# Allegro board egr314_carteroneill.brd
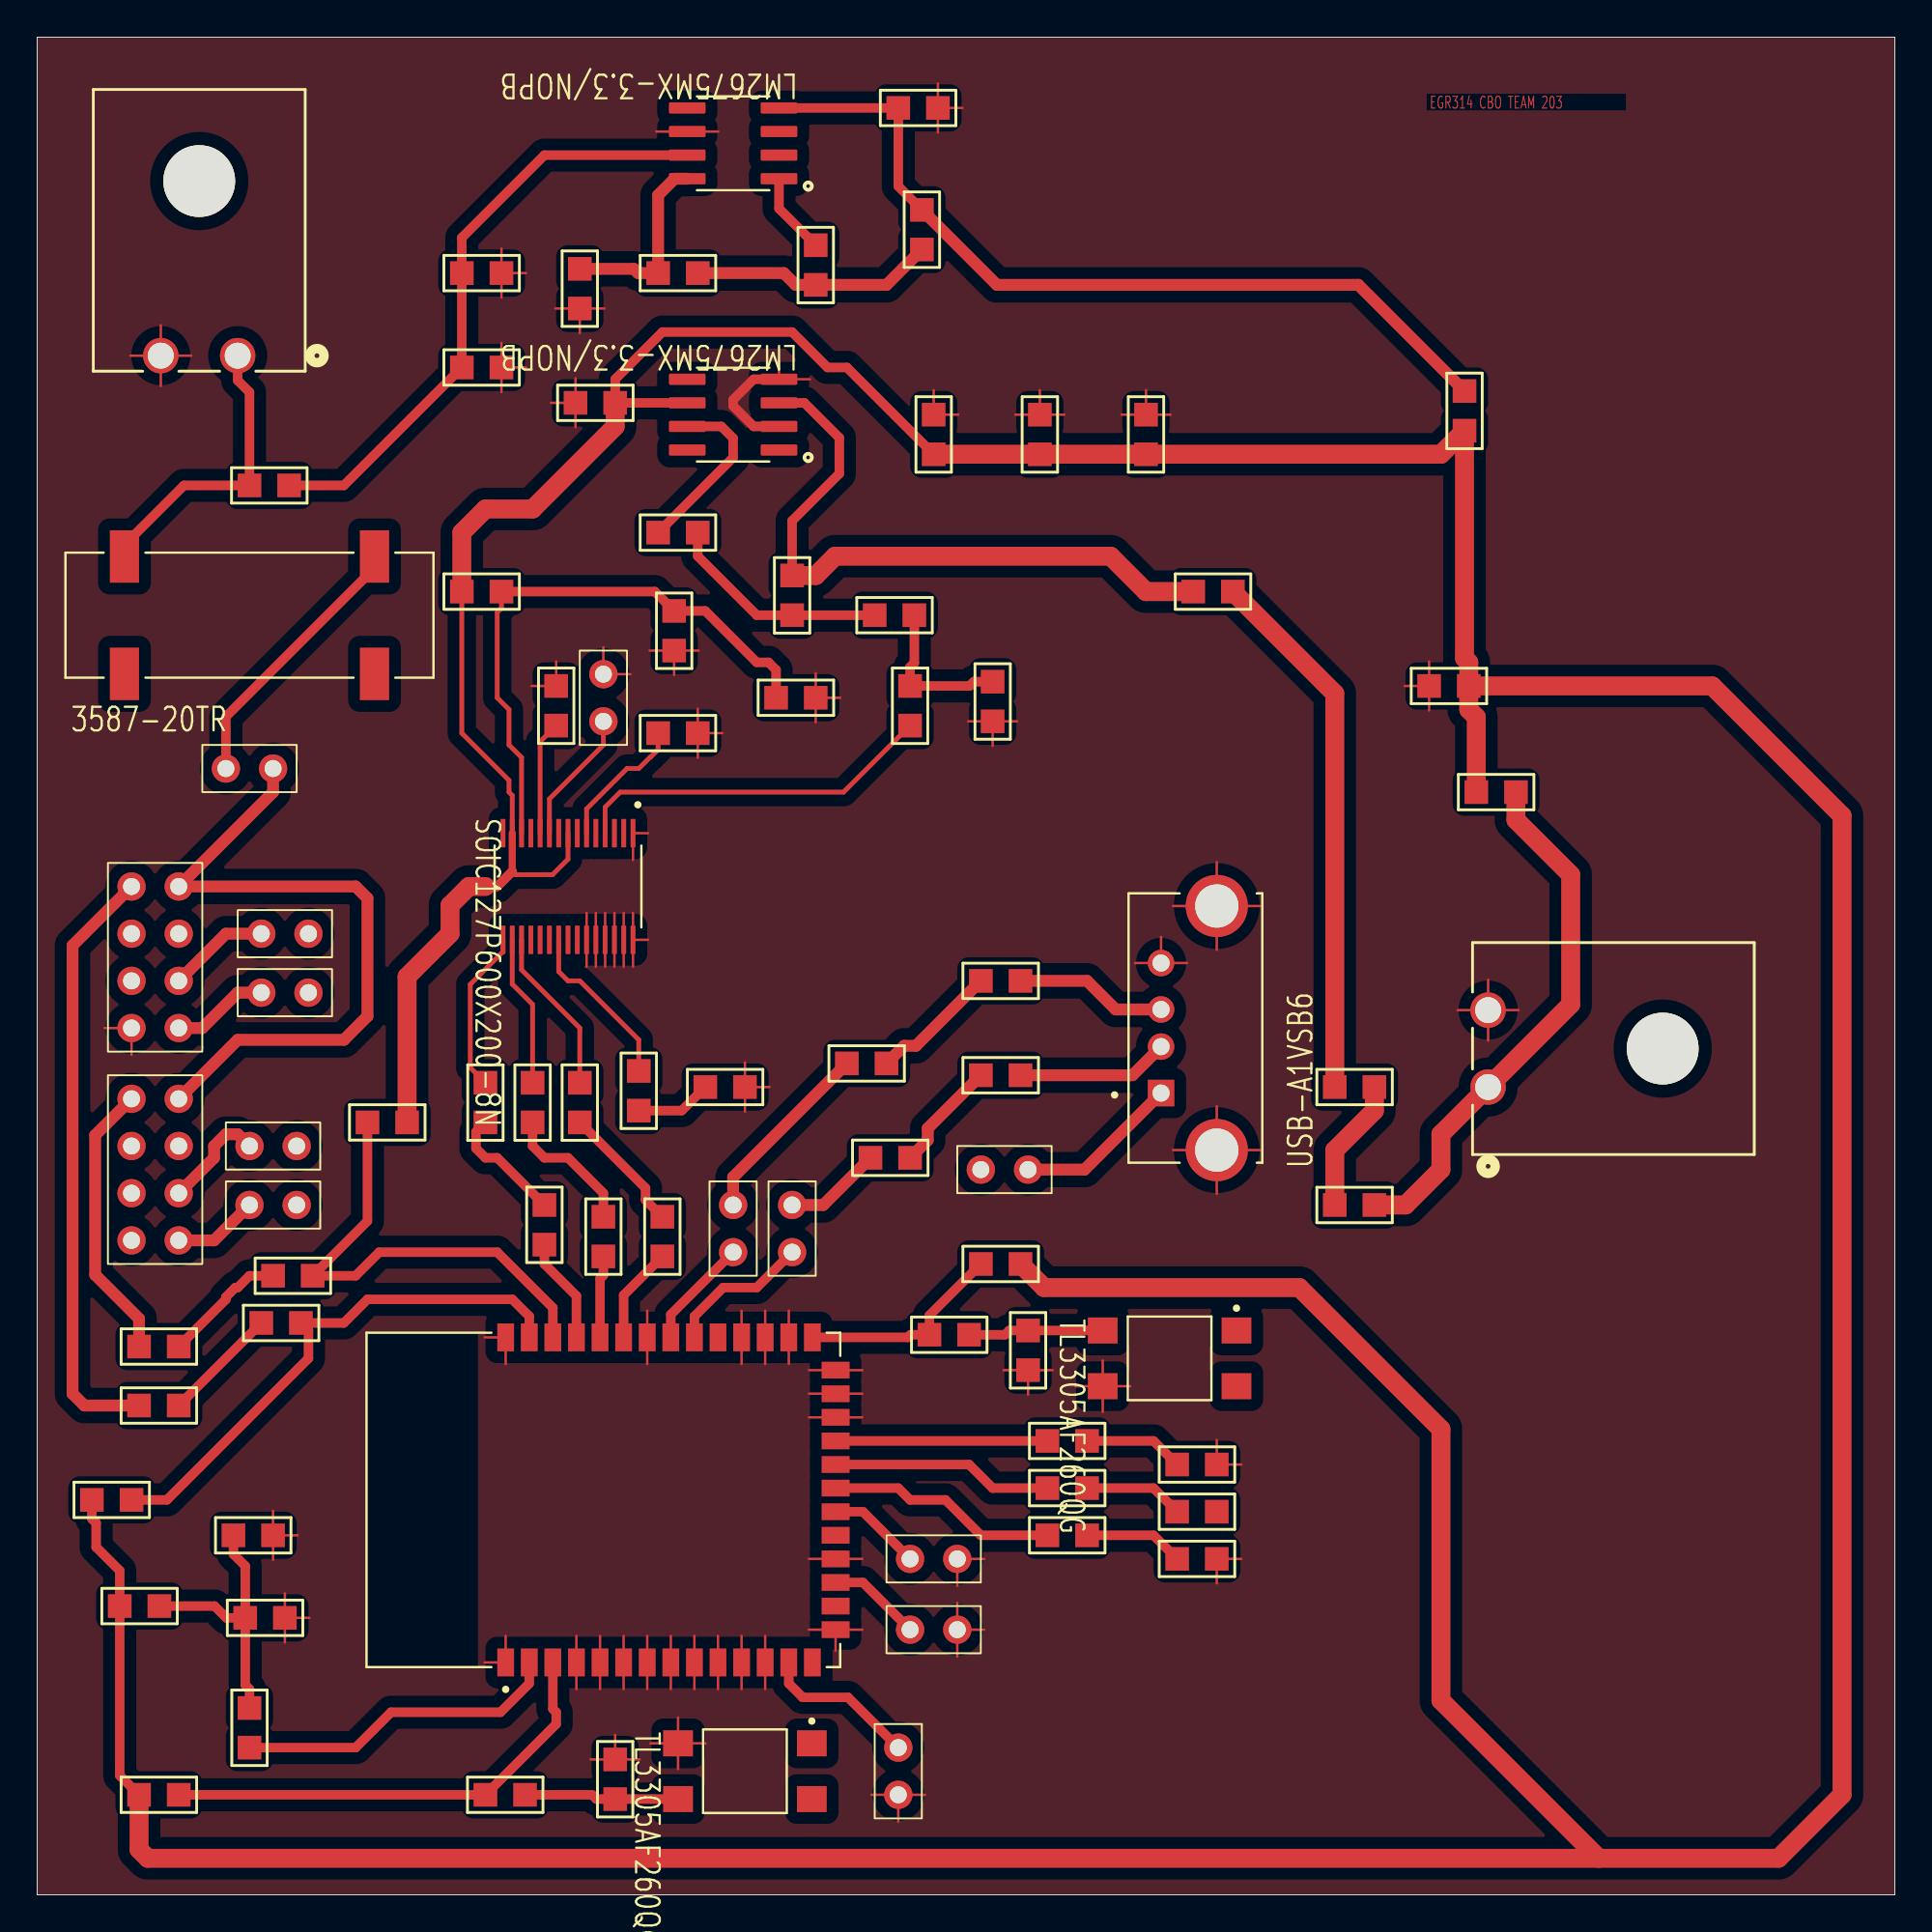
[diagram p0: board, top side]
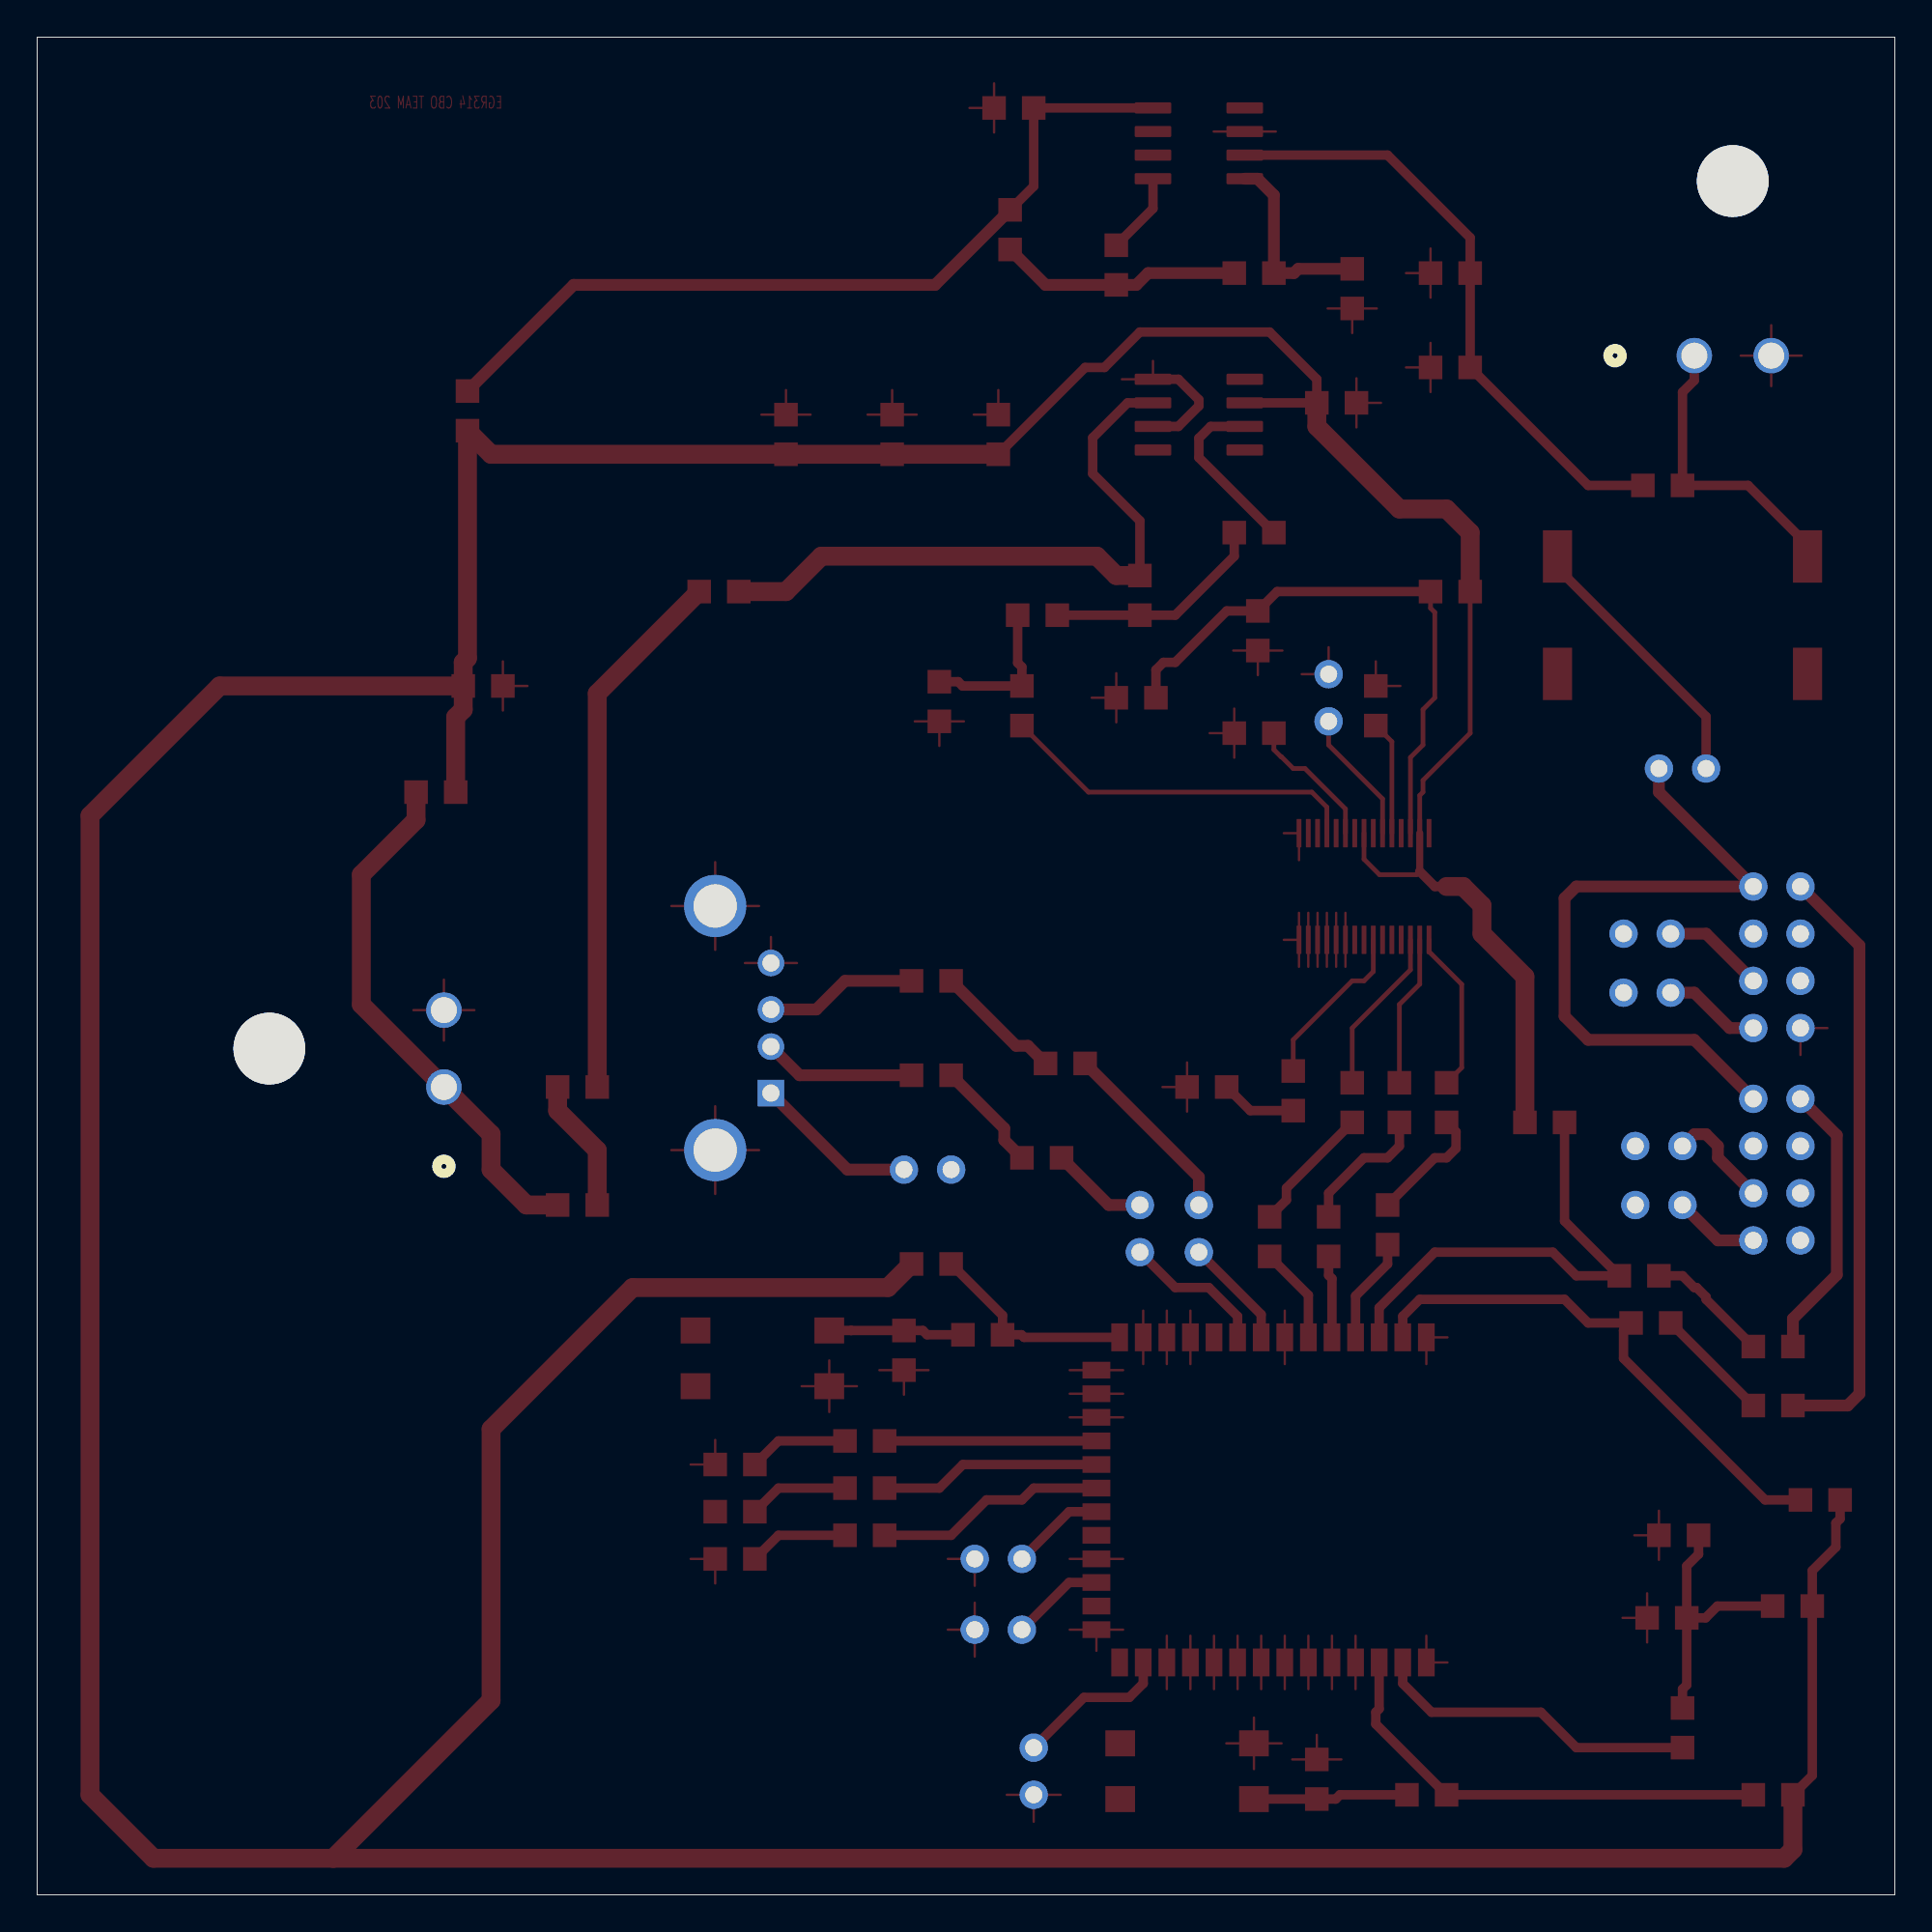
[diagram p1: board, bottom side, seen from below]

Outline 100 x 100 mm; copper layers: TOP, BOTTOM. Coordinates in mm from the lower left corner of the outline.
Outline path: 0,100 0,0 100,0 100,100 0,100

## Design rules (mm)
constraint set DEFAULT: min track width 0.127

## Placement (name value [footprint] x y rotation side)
C1  1uf  [SMC0805]  35.56 62.54 180 top
C2  10uf  [SMC0805]  53.98 79.68 270 top
C3  0.1uf  [SMC0805]  59.69 79.68 270 top
C4  10uf  [SMC0805]  41.91 64.44 180 top
C5  0.1uf  [SMC0805]  34.29 66.98 90 top
C6  10uf  [SMC0805]  48.26 79.68 270 top
C7  0.1uf  [SMC0805]  74.93 65.08 0 top
C8  1uf  [SMC0805]  27.94 65.08 270 top
C9  100uf/20V  [SMC0805]  22.86 87.3 0 top
C10  0.01uF  [SMC0805]  41.91 86.67 90 top
C11  594D 68uf/10V  [SMC0805]  46.35 96.19 0 top
C12  10uf/20V  [SMC0805]  22.86 82.22 0 top
C13  10uf  [SMC0805]  12.7 19.36 180 top
C14  0.1uf  [SMC0805]  13.34 14.91 180 top
C15  0.1uf  [SMC0805]  31.11 7.29 270 top
C16  0.5uF  [SMC0805]  51.44 63.17 90 top
C17  0.1uf  [SMC0805]  53.34 28.25 90 top
C18  1uf  [SMC0805]  69.85 37.14 0 top
C19  .1uf/20V  [SMC0805]  31.11 80.32 180 top
D1  LED  [SMR0805]  38.1 43.49 180 top
D2  SK12  [SMR0805]  29.21 85.4 90 top
D3  LED  [SMR0805]  63.5 18.09 180 top
D4  LED  [SMR0805]  63.5 20.63 180 top
D5  LED  [SMR0805]  63.5 23.17 180 top
F1  Fuse_CBO  [FUSE_3587-20TR]  11.43 68.89 0 top
F2  0.5A  [SMR0805]  4.45 15.55 0 top
J1  Input Header  [JUMPER8]  7.62 42.85 180 top
J2  JUMPER  [JUMPER2]  13.97 37.14 180 top
J3  JUMPER  [JUMPER2]  13.97 40.31 180 top
J4  JUMPER  [JUMPER2]  14.61 48.57 180 top
J5  JUMPER  [JUMPER2]  14.61 51.74 180 top
J6  Output Header  [JUMPER8]  7.62 54.28 180 top
J7  USB_Header_CBO  [ONSHORE_USB-A1VSB6]  63.5 46.66 90 top
J8  JUMPER  [JUMPER2]  10.16 60.63 0 top
J9  JUMPER  [JUMPER2]  50.8 39.04 0 top
J10  JUMPER  [JUMPER2]  30.48 63.17 90 top
J11  9V Barrel Jack  [CONN2_770966-2]  10.79 82.86 180 top
J12  JUMPER  [JUMPER2]  37.47 37.14 270 top
J13  JUMPER  [JUMPER2]  40.64 37.14 270 top
J14  JUMPER  [JUMPER2]  46.35 7.93 270 top
J15  JUMPER  [JUMPER2]  46.99 14.28 0 top
J16  JUMPER  [JUMPER2]  46.99 18.09 0 top
J17  Electret Microphone  [CONN2_770966-2]  78.11 43.49 90 top
L1  47uH  [SMR0805]  47.62 88.57 90 top
R1  0  [SMR0805]  7.62 29.52 180 top
R2  0  [SMR0805]  22.86 70.16 0 top
R3  400  [SMR0805]  32.38 42.22 90 top
R4  0  [SMR0805]  29.21 41.58 90 top
R5  0  [SMR0805]  50.8 49.2 0 top
R6  0  [SMR0805]  50.8 44.12 0 top
R7  0  [SMR0805]  26.67 41.58 90 top
R8  0  [SMR0805]  7.62 26.34 180 top
R9  0  [SMR0805]  24.13 41.58 90 top
R10  0  [SMR0805]  11.43 75.87 0 top
R11  0  [SMR0805]  76.83 80.95 270 top
R12  10K  [SMR0805]  7.62 5.39 180 top
R13  10K  [SMR0805]  50.8 33.96 0 top
R14  0  [SMR0805]  30.48 36.5 270 top
R15  10K  [SMR0805]  5.08 21.26 180 top
R16  0  [SMR0805]  35.56 87.3 180 top
R17  0  [SMR0805]  11.43 7.93 90 top
R18  10K  [SMR0805]  17.78 41.58 0 top
R19  0  [SMR0805]  27.3 37.14 270 top
R20  0  [SMR0805]  12.06 30.79 0 top
R21  0  [SMR0805]  24.13 5.39 0 top
R22  0  [SMR0805]  12.7 33.33 0 top
R23  0  [SMR0805]  33.66 36.5 270 top
R24  0  [SMR0805]  45.72 44.76 180 top
R25  0  [SMR0805]  46.99 39.68 180 top
R26  0  [SMR0805]  50.16 30.15 180 top
R27  RESISTOR TBD  [SMR0805]  40.64 68.89 90 top
R28  4K  [SMR0805]  45.09 68.89 0 top
R29  400  [SMR0805]  56.52 19.36 180 top
R30  400  [SMR0805]  56.52 21.9 180 top
R31  400  [SMR0805]  56.52 24.44 180 top
R32  0  [SMR0805]  35.56 73.33 180 top
R33  2.2k  [SMR0805]  77.47 59.36 0 top
R34  0  [SMR0805]  46.99 65.08 270 top
R35  0  [SMR0805]  69.85 43.49 0 top
R36  RESISTOR TBD  [SMR0805]  62.23 70.16 0 top
SW1  Pushbutton_CBO  [SW_TL3305AF260QG]  38.1 6.66 270 top
SW2  Pushbutton_CBO  [SW_TL3305AF260QG]  60.96 28.88 270 top
U1  PCM1861_CBO  [SOP50P640X120-30N]  28.57 54.28 270 top
U2  ESP32_WROOM_CBO  [XCVR_ESP32-S3-WROOM-1-N4]  30.48 21.26 90 top
U3  LM2675_CBO  [SOIC127P599X175-8N]  37.47 94.29 180 top
U4  TLV2371_CBO  [SOIC127P599X175-8N]  37.47 79.68 180 top

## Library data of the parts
C1-C8 C13-C18 = CAP NP
C9 C11 C12 C19 = CAP
C10 = CAPACITOR NON-POL
D1 D3-D5 = LED
D2 = DIODE SCHOTTKY
F1 = Fuse_CBO
F2 = FUSE
J1 J6 = CON8: User Part Number: ***
J2-J5 J8-J10 J12-J16 = JUMPER: User Part Number: ***
J7 = USB_Header_CBO
J11 J17 = CON2: User Part Number: PN; Tolerance: TOL
L1 = INDUCTOR
R1-R36 = RESISTOR
SW1 SW2 = Pushbutton_CBO
U1 = PCM1861_CBO
U2 = ESP32_WROOM_CBO
U3 = LM2675_CBO
U4 = TLV2371_CBO

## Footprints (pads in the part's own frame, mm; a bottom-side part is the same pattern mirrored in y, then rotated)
CONN2_770966-2
  round 3.861 hole 3.861 unplated: (2.07,-9.398)
  round 1.905 hole 1.397: 1(0,0) 2(4.14,0)
FUSE_3587-20TR
  rect 1.57x2.82 smd: 1_1(-6.73,3.16) 1_2(-6.73,-3.16) 2_1(6.73,3.16) 2_2(6.73,-3.16)
JUMPER2
  round 1.524 hole 0.914: 1(0,0) 2(2.54,0)
JUMPER8
  round 1.524 hole 0.914: 1(0,0) 2(2.54,0) 3(0,2.54) 4(2.54,2.54) 5(0,5.08) 6(2.54,5.08) 7(0,7.62) 8(2.54,7.62)
ONSHORE_USB-A1VSB6
  rect 1.428x1.428 hole 0.92: 1(-3.5,3)
  round 1.428 hole 0.92: 2(-1,3) 3(1,3) 4(3.5,3)
  round 3.346 hole 2.33: S1(-6.57,0) S2(6.57,0)
SMC0805
  rect 1.27x1.27 smd: 1(0,0) 2(2.134,0)
SMR0805
  rect 1.27x1.27 smd: 1(0,0) 2(2.134,0)
SOIC127P599X175-8N
  custom 0.15x0.15 smd: 1(-2.47,1.905) 2(-2.47,0.635) 3(-2.47,-0.635) 4(-2.47,-1.905) 5(2.47,-1.905) 6(2.47,-0.635) 7(2.47,0.635) 8(2.47,1.905)
SOP50P640X120-30N
  custom 0.065x0.065 smd: 1(-2.87,3.5) 2(-2.87,3) 3(-2.87,2.5) 4(-2.87,2) 5(-2.87,1.5) 6(-2.87,1) 7(-2.87,0.5) 8(-2.87,0) 9(-2.87,-0.5) 10(-2.87,-1) 11(-2.87,-1.5) 12(-2.87,-2) 13(-2.87,-2.5) 14(-2.87,-3) 15(-2.87,-3.5) 16(2.87,-3.5) 17(2.87,-3) 18(2.87,-2.5) 19(2.87,-2) 20(2.87,-1.5) 21(2.87,-1) 22(2.87,-0.5) 23(2.87,0) 24(2.87,0.5) 25(2.87,1) 26(2.87,1.5) 27(2.87,2) 28(2.87,2.5) 29(2.87,3) 30(2.87,3.5)
SW_TL3305AF260QG
  rect 1.4x1.6 smd: 1(-1.5,3.6) 2(-1.5,-3.6) 3(1.5,3.6) 4(1.5,-3.6)
XCVR_ESP32-S3-WROOM-1-N4
  rect 1.5x0.9 smd: 1(-8.75,5.26) 2(-8.75,3.99) 3(-8.75,2.72) 4(-8.75,1.45) 5(-8.75,0.18) 6(-8.75,-1.09) 7(-8.75,-2.36) 8(-8.75,-3.63) 9(-8.75,-4.9) 10(-8.75,-6.17) 11(-8.75,-7.44) 12(-8.75,-8.71) 13(-8.75,-9.98) 14(-8.75,-11.25) 27(8.75,-11.25) 28(8.75,-9.98) 29(8.75,-8.71) 30(8.75,-7.44) 31(8.75,-6.17) 32(8.75,-4.9) 33(8.75,-3.63) 34(8.75,-2.36) 35(8.75,-1.09) 36(8.75,0.18) 37(8.75,1.45) 38(8.75,2.72) 39(8.75,3.99) 40(8.75,5.26)
  rect 0.9x1.5 smd: 15(-6.985,-12.5) 16(-5.715,-12.5) 17(-4.445,-12.5) 18(-3.175,-12.5) 19(-1.905,-12.5) 20(-0.635,-12.5) 21(0.635,-12.5) 22(1.905,-12.5) 23(3.175,-12.5) 24(4.445,-12.5) 25(5.715,-12.5) 26(6.985,-12.5)

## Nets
3.3V POWER: C2.2 C3.2 C6.2 C7.2 C19.1 F2.1 R2.1 R11.2 R12.2 R13.2 R15.2 R18.2 R33.1 U1.8 U1.14 U4.6(VDD)
GND_POWER: C1.1 C2.1 C3.1 C4.1 C5.1 C6.1 C7.1 C8.1 C9.2 C11.2 C12.2 C13.1 C14.1 C15.1 C16.1 C17.1 C19.2 D1.1(CATHODE) D2.1 D3.1(CATHODE) D4.1(CATHODE) D5.1(CATHODE) J1.8 J6.8 J7.4 J7.S1(SHIELD) J7.S2 J10.2 J11.2 J14.2 J15.2 J16.2 J17.2 SW1.2 SW2.4(4B) U1.1 U1.2 U1.3 U1.7 U1.9(XO) U1.12 U1.15 U1.19 U1.20 U1.21 U1.23 U1.24 U1.25 U1.26 U1.27 U1.28 U1.29 U1.30 U2.1 U2.4 U2.5 U2.6 U2.7 U2.8 U2.9 U2.10 U2.11 U2.12 U2.14 U2.15 U2.16 U2.18 U2.19 U2.24 U2.25 U2.26 U2.28 U2.29 U2.30 U2.31 U2.34 U2.40 U3.6 U4.2 U4.4
DATA+: R5.1 R24.1
DATA-: R6.1 R25.1
DIN: R4.1 R23.1
LOWPASS OUT: R34.2 U1.4
MCLK: R7.1 R14.1
MIC OUT: C18.1 R35.2
OPAMP OUT: R27.1 R28.1 R32.1
POWER 9V: F1.1_1 J11.1 R10.1
UART IN: R1.1 R22.1
UART OUT: R8.1 R20.1
WS: R9.1 R19.1
N00606: C9.1 C12.1 R10.2 U3.7
N00781: D2.2(CATHODE) R16.2 U3.8(VOUT)
N00783: C10.1 L1.1 R16.1
N00788: C10.2 U3.1
N00918: C11.1 L1.2 R11.1 U3.4
N07817: J1.1 J6.1 J8.2
N09843: J6.2 R8.2
N21699: J1.2 R1.2
N22060: F1.2_1(2) J8.1
N22626: J7.2 R6.2
N22652: J7.3 R5.2
N22917: J7.1 J9.2
N24434: J1.7 J2.2
N24454: J4.2 J6.7
N24458: J5.2 J6.5
N24715: J1.5 J3.2
N26680: C18.2 J17.1 R33.2
N29485: R27.2 R36.1 U4.3
N29573: R32.2 U4.7
N34669: C16.2 R28.2 R34.1
N36501: C4.2 C5.2 R2.2 U1.13
N37158: C1.2 U1.6
N37386: C8.2 U1.11
N38649: J10.1 U1.10
N39459: R9.2 U1.16
N39468: R7.2 U1.17
N39483: R4.2 U1.18
N40504: D1.2 R3.1
N40674: R3.2 U1.22
N41571: R15.1 R20.2 U2.39
N41575: R18.1 R22.2 U2.38
N41673: C13.2 C14.2 F2.2 R17.2
N43009: R12.1 R21.1 U2.3
N43015: C15.2 R21.2 SW1.4(4B)
N44695: R14.2 U2.36
N44721: R19.2 U2.37
N46155: R23.2 U2.35
N46205: J16.1 U2.20
N46209: J15.1 U2.17
N46676: J14.1 U2.13
N51510: R31.2 U2.23
N51528: R30.2 U2.22
N51546: R29.2 U2.21
N53013: J12.1 R24.2
N53017: J13.1 R25.2
N53033: J12.2 U2.33
N53151: R13.1 R26.2 U2.27
N53160: C17.2 R26.1 SW2.2
N53179: J13.2 U2.32
N71514: R35.1 R36.2
N73812: R17.1 U2.2(VDD33)
N490120: D5.2 R31.1
N508940: D4.2 R30.1
N512210: D3.2 R29.1

Pads without a net: F1 1_2 2_2; J1 3 4 6; J2 1; J3 1; J4 1; J5 1; J6 3 4 6; J9 1; SW1 1 3; SW2 1 3; U1 5; U3 2 3 5; U4 1 5 8

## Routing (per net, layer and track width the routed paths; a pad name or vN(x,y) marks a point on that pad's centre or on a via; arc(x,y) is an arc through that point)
3.3V POWER: length 369.5
  TOP w0.254: 25.58,55.09 25.75,54.92 27.74,54.92 28.57,55.75 U1.8 ; R2.1 22.86,62.54 25.4,60 25.4,59.36 25.58,59.19 U1.14
  TOP w0.381: U1.14 25.58,55.09
  TOP w0.508: 24.13,54.28 24.77,54.28 25.58,55.09 ; U4.6 C19.1 31.11,81.59 33.66,84.13 40.64,84.13 42.55,82.22 43.59,82.22 C6.2 ; R15.2 2.95,20.24 3.17,20.02 3.17,18.72 4.45,17.45 F2.1 4.45,6.43 R12.2
  TOP w1.016: C7.2 77.06,66.35 76.83,66.57 R11.2 75.56,77.55 C3.2 C2.2 C6.2 ; C7.2 90.17,65.08 97.16,58.09 97.16,5.39 93.74,1.97 84.06,1.97 ; C7.2 77.06,63.81 77.47,63.4 R33.1 ; R2.1 22.86,73.33 24.13,74.6 26.67,74.6 31.11,79.05 C19.1 ; R13.2 54.2,32.69 67.94,32.69 75.56,25.07 75.56,10.47 84.06,1.97 ; R18.2 19.91,49.43 22.23,51.74 22.23,53.26 23.24,54.28 24.13,54.28 ; 84.06,1.97 5.96,1.97 5.49,2.44 R12.2
GND_POWER: length 233.7
  TOP w0.127: 78.11,45.99 J17.2 ; J17.2 78.11,49.26 ; J17.2 79.74,47.62 ; J17.2 76.47,47.62 ; U2.15 44.42,14.28 ; U2.15 41.54,14.28 ; U2.15 42.98,13.14 ; 39.19,28.57 U2.29 39.19,31.45 ; 39.19,11.07 U2.12 39.19,13.95 ; J11.2 8.29,82.86 ; J11.2 6.66,81.22 ; J11.2 6.66,84.49 ; J11.2 5.02,82.86 ; 24.99,85.98 C9.2 ; C9.2 24.99,88.62 ; C9.2 26.31,87.3 ; 27.94,66.4 C8.1 26.62,65.08 ; 34.11,11.07 U2.8 34.11,13.95 ; 48.26,81 C6.1 49.58,79.68 ; 12.7,18.03 C13.1 ; C13.1 12.7,20.68 ; C13.1 14.02,19.36 ; 32.84,13.95 U2.7 32.84,11.07 ; SW2.4 57.36,28.77 ; SW2.4 57.36,25.99 ; SW2.4 55.87,27.38 ; SW2.4 58.85,27.38 ; 27.66,80.32 C19.2 ; C19.2 28.98,81.64 ; C19.2 28.98,78.99 ; C4.1 41.91,65.76 ; C4.1 43.23,64.44 ; C4.1 41.91,63.12 ; 29.79,7.29 C15.1 ; C15.1 31.11,8.61 ; C15.1 32.44,7.29 ; 52.65,79.68 C2.1 ; C2.1 55.3,79.68 ; C2.1 53.98,81 ; 3.63,46.66 J6.8 5.08,45.21 ; C3.1 61.01,79.68 ; C3.1 58.37,79.68 ; C3.1 59.69,81 ; D1.1 38.1,44.81 ; D1.1 39.42,43.49 ; D1.1 38.1,42.16 ; 29.03,11.07 U2.4 29.03,13.95 ; J15.2 49.53,15.72 ; J15.2 49.53,12.83 ; J15.2 50.98,14.28 ; 61.14,53.23 J7.S2 ; J7.S2 63.5,50.87 ; J7.S2 63.5,55.59 ; J7.S2 65.86,53.23 ; 30.48,67.16 J10.2 31.93,65.71 ; 46.35,3.94 J14.2 ; J14.2 44.91,5.39 ; J14.2 47.8,5.39 ; 64.82,23.17 D5.1 63.5,24.49 ; 36.65,13.95 U2.10 36.65,11.07 ; 36.67,94.92 U3.6 33.32,94.92 ; SW1.2 34.5,9.54 ; SW1.2 34.5,6.77 ; SW1.2 33.01,8.16 ; SW1.2 35.99,8.16 ; 41.54,25.71 U2.24 44.42,25.71 ; 44.42,18.09 U2.18 41.54,18.09 ; J7.4 60.5,51.56 ; J7.4 59.1,50.16 ; J7.4 61.9,50.16 ; 74.93,63.75 C7.1 ; C7.1 73.61,65.08 ; C7.1 74.93,66.4 ; 31.57,49.96 U1.29 31.57,52.86 ; 37.92,13.95 U2.11 37.92,11.07 ; 32.97,66.98 C5.1 ; C5.1 35.61,66.98 ; C5.1 34.29,65.66 ; 29.57,49.96 U1.25 29.57,52.86 ; 29.21,84.07 D2.1 ; D2.1 30.53,85.4 ; D2.1 27.89,85.4 ; 31.57,13.95 U2.6 31.57,11.07 ; 44.42,28.25 U2.26 41.54,28.25 ; U1.30 32.89,51.41 ; U1.30 32.08,49.96 ; U1.30 32.08,52.86 ; 63.5,37.73 J7.S1 ; J7.S1 61.14,40.09 ; J7.S1 65.86,40.09 ; J7.S1 63.5,42.45 ; 30.57,49.96 U1.27 30.57,52.86 ; 30.08,49.96 U1.26 30.08,52.86 ; 25.22,13.95 U2.1 24.08,12.51 ; 30.3,11.07 U2.5 30.3,13.95 ; 32.89,57.15 U1.1 32.08,55.7 ; 63.5,16.76 D3.1 64.82,18.09 ; 53.34,26.92 C17.1 ; C17.1 52.02,28.25 ; C17.1 54.66,28.25 ; 32.84,31.45 U2.34 32.84,28.57 ; 24.08,30.01 U2.40 25.22,28.57 ; 31.08,49.96 U1.28 31.08,52.86 ; C14.1 13.34,16.23 ; C14.1 14.66,14.91 ; C14.1 13.34,13.59 ; 50.98,18.09 J16.2 49.53,16.64 ; 44.42,26.98 U2.25 41.54,26.98 ; 39.93,82.57 U4.4 41.61,81.59 ; 35.56,61.21 C1.1 ; C1.1 35.56,63.86 ; C1.1 36.88,62.54 ; 50.11,63.17 C16.1 ; C16.1 52.76,63.17 ; C16.1 51.44,61.85 ; 48.49,94.87 C11.2 ; C11.2 48.49,97.51 ; C11.2 49.81,96.19 ; C12.2 26.31,82.22 ; C12.2 24.99,80.9 ; C12.2 24.99,83.54 ; 40.46,31.45 U2.28 40.46,28.57 ; 37.92,31.45 U2.30 37.92,28.57 ; 35.38,11.07 U2.9 35.38,13.95
  TOP w0.508: U4.4 38.57,81.59 37.47,80.48 37.47,80.15 38.57,79.05 U4.2
DATA+: length 6.9
  TOP w0.635: R5.1 47.3,45.7 46.67,45.7 R24.1
DATA-: length 6
  TOP w0.635: R6.1 47.94,41.26 47.94,40.62 R25.1
DIN: length 6.9
  TOP w0.508: R23.1 32.75,37.4 32.75,38.04 R4.1
LOWPASS OUT: length 19.6
  TOP w0.254: R34.2 43.41,59.36 31.38,59.36 30.57,58.55 U1.4
MCLK: length 7.4
  TOP w0.508: R14.1 30.48,37.77 28.57,39.68 27.3,39.68 26.67,40.31 R7.1
MIC OUT: length 7.2
  TOP w1.016: C18.1 69.85,40.08 71.98,42.22 R35.2
OPAMP OUT: length 12.1
  TOP w0.508: R32.1 35.56,72.06 38.73,68.89 R27.1 R28.1
POWER 9V: length 15.9
  TOP w0.508: F1.1_1 4.7,72.67 7.9,75.87 R10.1 11.43,80.89 10.79,81.52 J11.1
UART IN: length 6.7
  TOP w0.508: R22.1 11.43,33.33 10.79,32.69 10.67,32.69 10.16,32.18 10.16,32.06 R1.1
UART OUT: length 6.3
  TOP w0.508: R8.1 R20.1
WS: length 6.6
  TOP w0.508: R9.1 23.62,41.07 23.62,40.18 24.13,39.68 24.77,39.68 R19.1
N00606: length 32.9
  TOP w0.508: U3.7 27.3,93.65 22.86,89.21 C9.1 C12.1 16.51,75.87 R10.2
N00781: length 10.4
  TOP w0.635: D2.2 32.12,87.53 32.35,87.3 R16.2 33.43,91.5 34.31,92.38 U3.8
N00783: length 13.1
  TOP w0.635: L1.1 45.72,86.67 C10.1 40.83,86.67 40.2,87.3 R16.1
N00788: length 4.4
  TOP w0.508: U3.1 39.93,90.77 C10.2
N00918: length 45.7
  TOP w0.508: L1.2 46.35,91.97 C11.1 U3.4
  TOP w0.635: R11.1 71.12,86.67 51.66,86.67 L1.2
N07817: length 37.2
  TOP w0.635: J1.1 10.79,46.03 16.51,46.03 17.78,47.3 17.78,53.65 17.14,54.28 J6.1 12.7,59.36 J8.2
N09843: length 32.5
  TOP w0.635: J6.2 1.91,51.11 1.91,26.98 2.54,26.34 R8.2
N21699: length 15.1
  TOP w0.635: J1.2 3.12,40.89 3.12,33.38 5.49,31.01 R1.2
N22060: length 14.7
  TOP w0.508: J8.1 10.16,63.42 18.16,71.42 F1.2_1
N22626: length 8.2
  TOP w0.635: J7.2 58.96,44.12 R6.2
N22652: length 8.2
  TOP w0.635: J7.3 58.06,47.66 56.52,49.2 R5.2
N22917: length 8.9
  TOP w0.635: J9.2 56.38,39.04 J7.1
N24434: length 4.6
  TOP w0.635: J2.2 9.53,35.23 J1.7
N24454: length 5.2
  TOP w0.635: 12.06,48.57 10.79,48.57 8.89,46.66 J6.7
N24458: length 5.5
  TOP w0.635: 12.06,51.74 10.16,51.74 J6.5
N24715: length 5.8
  TOP w0.635: J3.2 10.79,40.95 10.16,40.95 9.53,40.31 9.53,39.68 J1.5
N26680: length 28.8
  TOP w1.016: R33.2 79.6,57.86 82.55,54.92 82.55,47.93 J17.1 75.56,40.95 75.56,39.04 73.66,37.14 C18.2
N29485: length 35.3
  TOP w0.508: U4.3 41.3,80.32 43.18,78.44 43.18,76.51 40.64,73.97 R27.2
  TOP w1.016: R36.1 59.69,70.16 57.78,72.06 42.95,72.06 41.91,71.02 R27.2
N29573: length 9.5
  TOP w0.508: R32.2 37.47,77.37 37.47,78.41 36.83,79.05 U4.7
N34669: length 8.4
  TOP w0.508: R28.2 47.22,66.32 46.99,66.09 R34.1 50.19,65.08 50.42,65.3 C16.2
N36501: length 31.7
  TOP w0.254: R2.2 24.99,69.27 24.77,69.04 24.77,64.44 25.4,63.81 25.4,61.9 26.07,61.23 U1.13
  TOP w0.508: R2.2 33.25,70.16 C5.2 35.97,69.11 38.73,66.35 39.37,66.35 39.78,65.94 C4.2
N37158: length 7.4
  TOP w0.254: U1.6 29.57,58.46 31.75,60.63 32.38,60.63 33.02,61.27 33.05,61.27 33.43,61.65 C1.2
N37386: length 6.1
  TOP w0.254: C8.2 27.07,62.08 U1.11
N38649: length 7.2
  TOP w0.254: J10.1 30.48,61.9 27.58,59 U1.10
N39459: length 8.8
  TOP w0.254: R9.2 23.32,44.53 23.32,49.02 25.07,50.78 U1.16
N39468: length 8.2
  TOP w0.254: R7.2 26.67,47.93 25.58,49.03 U1.17
N39483: length 9
  TOP w0.254: R4.2 29.21,46.66 26.07,49.8 U1.18
N40504: length 4.1
  TOP w0.508: R3.1 34.7,42.22 D1.2
N40674: length 9.2
  TOP w0.254: R3.2 32.38,46.03 29.21,49.2 28.57,49.2 28.07,49.7 U1.22
N41571: length 29.1
  TOP w0.508: U2.39 26.49,31.14 25.58,32.06 17.78,32.06 16.51,30.79 R20.2 14.61,30.38 14.61,28.88 6.99,21.26 R15.1
N41575: length 25.8
  TOP w0.508: R18.1 17.78,36.27 R22.2 17.14,33.33 18.41,34.6 24.77,34.6 27.76,31.6 U2.38
N41673: length 14.5
  TOP w0.508: R17.2 11.43,11.07 11.2,11.3 C14.2 ; C13.2 10.57,18.34 11.2,17.7 C14.2 ; C14.2 10.19,14.91 9.55,15.55 F2.2
N43009: length 25.3
  TOP w0.508: U2.3 27.76,10.01 27.94,9.83 27.94,9.2 R21.1 R12.1
N43015: length 8.3
  TOP w0.508: SW1.4 33.95,5.15 33.95,5.16 C15.2 30.1,5.16 29.87,5.39 R21.2
N44695: length 4.4
  TOP w0.508: U2.36 30.3,33.17 30.48,33.35 R14.2
N44721: length 5.7
  TOP w0.508: U2.37 29.03,32.24 27.3,33.96 R19.2
N46155: length 5.2
  TOP w0.508: R23.2 31.57,32.28 U2.35
N46205: length 5.1
  TOP w0.508: J16.1 44.45,20.63 U2.20
N46209: length 5.1
  TOP w0.508: J15.1 44.45,16.82 U2.17
N46676: length 8.5
  TOP w0.508: U2.13 40.46,11.38 41.21,10.63 43.65,10.63 J14.1
N51510: length 11.4
  TOP w0.508: U2.23 R31.2
N51528: length 11.9
  TOP w0.508: R30.2 51.44,21.9 50.16,23.17 U2.22
N51546: length 12.5
  TOP w0.508: U2.21 46.35,21.9 46.99,21.26 48.9,21.26 50.8,19.36 R29.2
N53013: length 10.2
  TOP w0.635: J12.1 37.47,38.63 R24.2
N53017: length 5.3
  TOP w0.635: J13.1 42.32,37.14 R25.2
N53033: length 6
  TOP w0.508: J12.2 34.11,31.24 U2.33
N53151: length 11.3
  TOP w0.508: R13.1 48.03,31.19 R26.2 47.02,30.15 46.88,30.01 U2.27
N53160: length 7.3
  TOP w0.508: R26.1 52.1,30.15 52.32,30.38 C17.2 56.18,30.38 56.18,30.38 SW2.2
N53179: length 7.8
  TOP w0.508: U2.32 35.38,31.14 36.93,32.69 38.73,32.69 J13.2
N71514: length 28.9
  TOP w1.016: R36.2 69.85,64.67 R35.1
N73812: length 17.6
  TOP w0.508: R17.1 17.14,7.93 19.05,9.83 24.94,9.83 26.49,11.38 U2.2
N490120: length 5.4
  TOP w0.508: R31.1 60.1,24.44 D5.2
N508940: length 5.4
  TOP w0.508: R30.1 60.1,21.9 D4.2
N512210: length 5.4
  TOP w0.508: D3.2 60.1,19.36 R29.1

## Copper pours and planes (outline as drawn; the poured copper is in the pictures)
GND_POWER on TOP: 100,0 100,100 0,100 0,0

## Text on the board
TOP: EGR314 CBO TEAM 203
